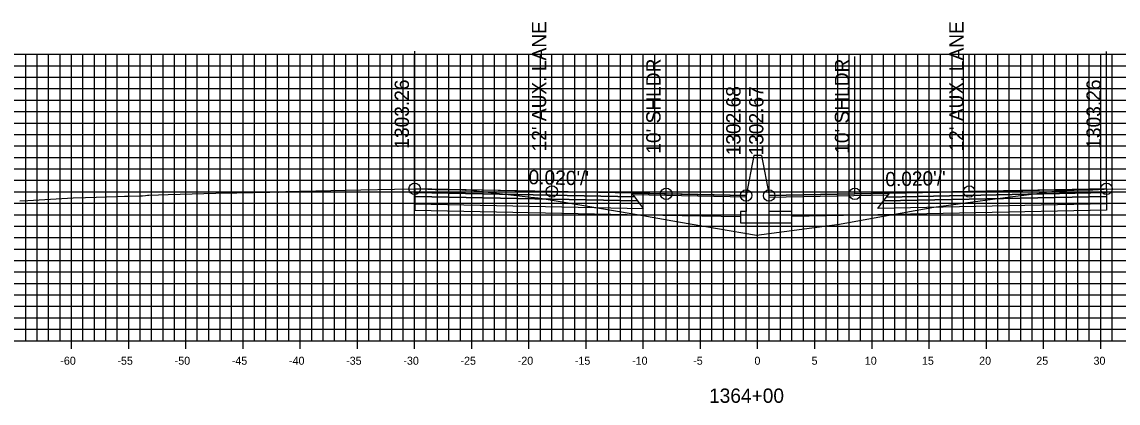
# Model space of a CAD drawing. Extents: x 674939 to 678919, y 750652 to 765176.
# Drawn here: x 678674.2 to 678770, y 754207.1 to 754240.4 of the extents above; entities that cross this region are included whole.
import ezdxf

# ---------------------------------------------------------------- set-up
doc = ezdxf.new("R2010")
doc.units = 0
for name, color, linetype in [('R_Alt Surface', 7, 'Continuous'), ('R_Axis', 7, 'Continuous'), ('R_Axis Annot', 7, 'Continuous'), ('R_Exist Surface', 7, 'Continuous'), ('R_Fin Surface', 7, 'Continuous'), ('R_Grid', 7, 'Continuous'), ('R_No Plot', 7, 'Continuous'), ('R_Proposed Road', 7, 'Continuous'), ('R_Xsect Elev', 7, 'Continuous'), ('R_Xsect Slope', 7, 'Continuous')]:
    doc.layers.add(name, color=color, linetype=linetype)

msp = doc.modelspace()

# ---------------------------------------------------------------- linework, layer by layer
at = {"layer": 'R_Alt Surface'}
for points in [[(678708.541, 754225.481), (678708.541, 754225.151), (678728.041, 754224.761), (678727.791, 754225.096)], [(678769.035, 754225.477), (678769.035, 754225.147), (678749.535, 754224.757), (678749.785, 754225.092)], [(678708.541, 754225.151), (678708.541, 754224.491), (678728.541, 754224.091), (678728.041, 754224.761)], [(678769.035, 754225.147), (678769.035, 754224.487), (678749.035, 754224.087), (678749.535, 754224.757)]]:
    msp.add_lwpolyline(points, close=True, dxfattribs=at)
for points in [[(678708.541, 754224.491), (678708.541, 754223.951), (678728.541, 754223.551), (678737.033, 754223.381)], [(678769.035, 754224.487), (678769.035, 754223.947), (678749.035, 754223.547), (678741.533, 754223.397)]]:
    msp.add_lwpolyline(points, dxfattribs=at)
at = {"layer": 'R_Axis'}
for p, q in [((678678.533, 754211.851), (678678.533, 754213.251)), ((678683.533, 754211.851), (678683.533, 754213.251)), ((678688.533, 754211.851), (678688.533, 754213.251)), ((678693.533, 754211.851), (678693.533, 754213.251)), ((678698.533, 754211.851), (678698.533, 754213.251)), ((678703.533, 754211.851), (678703.533, 754213.251)), ((678708.533, 754211.851), (678708.533, 754213.251)), ((678713.533, 754211.851), (678713.533, 754213.251)), ((678718.533, 754211.851), (678718.533, 754213.251)), ((678723.533, 754211.851), (678723.533, 754213.251)), ((678728.533, 754211.851), (678728.533, 754213.251)), ((678733.533, 754211.851), (678733.533, 754213.251)), ((678738.533, 754211.851), (678738.533, 754213.251)), ((678743.533, 754211.851), (678743.533, 754213.251)), ((678748.533, 754211.851), (678748.533, 754213.251)), ((678753.533, 754211.851), (678753.533, 754213.251)), ((678758.533, 754211.851), (678758.533, 754213.251)), ((678763.533, 754211.851), (678763.533, 754213.251)), ((678768.533, 754211.851), (678768.533, 754213.251)), ((678638.533, 754212.551), (678838.533, 754212.551))]:
    msp.add_line(p, q, dxfattribs=at)
at = {"layer": 'R_Exist Surface'}
msp.add_lwpolyline([(678673.999, 754224.758), (678674.713, 754224.799), (678678.665, 754225.008), (678679.762, 754225.051), (678682.52, 754225.137), (678683.178, 754225.161), (678683.562, 754225.167), (678684.578, 754225.193), (678684.733, 754225.203), (678684.998, 754225.231), (678685.168, 754225.249), (678685.288, 754225.257), (678686.989, 754225.307), (678692.214, 754225.446), (678692.982, 754225.461), (678695.885, 754225.521), (678696.434, 754225.534), (678696.579, 754225.513), (678696.633, 754225.508), (678697.069, 754225.559), (678697.288, 754225.577), (678703.822, 754225.711), (678706.783, 754225.776), (678708.456, 754225.812), (678708.541, 754225.811), (678708.61, 754225.812), (678708.744, 754225.809), (678709.018, 754225.797), (678710.324, 754225.755), (678710.599, 754225.757), (678710.763, 754225.747), (678712.65, 754225.708), (678712.979, 754225.698), (678713.034, 754225.693), (678713.163, 754225.731), (678713.208, 754225.732), (678718.707, 754225.088), (678719.337, 754225.022), (678721.098, 754224.728), (678727.997, 754223.552), (678731.621, 754222.937), (678738.446, 754221.755), (678743.262, 754222.411), (678745.702, 754222.716), (678748.719, 754223.267), (678753.939, 754224.213), (678757.983, 754224.76), (678760.614, 754225.114), (678762.283, 754225.313), (678764.89, 754225.656), (678764.959, 754225.64), (678766.212, 754225.692), (678766.943, 754225.715), (678767.831, 754225.733), (678768.343, 754225.743), (678768.828, 754225.785), (678769.035, 754225.807), (678769.057, 754225.809), (678769.07, 754225.81), (678771.354, 754225.772)], dxfattribs=at)
at = {"layer": 'R_Fin Surface'}
for points in [[(678737.533, 754225.231), (678730.541, 754225.371), (678720.541, 754225.571), (678708.541, 754225.811)], [(678769.035, 754225.807), (678757.035, 754225.567), (678747.035, 754225.367), (678739.533, 754225.217)]]:
    msp.add_lwpolyline(points, dxfattribs=at)
for points in [[(678708.541, 754225.811), (678708.541, 754225.481), (678727.791, 754225.096), (678727.541, 754225.431)], [(678727.541, 754225.431), (678737.533, 754225.231), (678737.537, 754225.073), (678727.661, 754225.271)], [(678749.916, 754225.267), (678739.533, 754225.059), (678739.533, 754225.217), (678750.035, 754225.427)], [(678769.035, 754225.807), (678769.035, 754225.477), (678749.785, 754225.092), (678750.035, 754225.427)]]:
    msp.add_lwpolyline(points, close=True, dxfattribs=at)
at = {"layer": 'R_Grid'}
for p, q in [((678638.533, 754237.551), (678838.533, 754237.551)), ((678674.533, 754212.551), (678674.533, 754237.551)), ((678675.533, 754212.551), (678675.533, 754237.551)), ((678676.533, 754212.551), (678676.533, 754237.551)), ((678677.533, 754212.551), (678677.533, 754237.551)), ((678678.533, 754212.551), (678678.533, 754237.551)), ((678679.533, 754212.551), (678679.533, 754237.551)), ((678680.533, 754212.551), (678680.533, 754237.551)), ((678681.533, 754212.551), (678681.533, 754237.551)), ((678682.533, 754212.551), (678682.533, 754237.551)), ((678683.533, 754212.551), (678683.533, 754237.551)), ((678684.533, 754212.551), (678684.533, 754237.551)), ((678685.533, 754212.551), (678685.533, 754237.551)), ((678686.533, 754212.551), (678686.533, 754237.551)), ((678687.533, 754212.551), (678687.533, 754237.551)), ((678688.533, 754212.551), (678688.533, 754237.551)), ((678689.533, 754212.551), (678689.533, 754237.551)), ((678690.533, 754212.551), (678690.533, 754237.551)), ((678691.533, 754212.551), (678691.533, 754237.551)), ((678692.533, 754212.551), (678692.533, 754237.551)), ((678693.533, 754212.551), (678693.533, 754237.551)), ((678694.533, 754212.551), (678694.533, 754237.551)), ((678695.533, 754212.551), (678695.533, 754237.551)), ((678696.533, 754212.551), (678696.533, 754237.551)), ((678697.533, 754212.551), (678697.533, 754237.551)), ((678698.533, 754212.551), (678698.533, 754237.551)), ((678699.533, 754212.551), (678699.533, 754237.551)), ((678700.533, 754212.551), (678700.533, 754237.551)), ((678701.533, 754212.551), (678701.533, 754237.551)), ((678702.533, 754212.551), (678702.533, 754237.551)), ((678703.533, 754212.551), (678703.533, 754237.551)), ((678704.533, 754212.551), (678704.533, 754237.551)), ((678705.533, 754212.551), (678705.533, 754237.551)), ((678706.533, 754212.551), (678706.533, 754237.551)), ((678707.533, 754212.551), (678707.533, 754237.551)), ((678708.533, 754212.551), (678708.533, 754237.551)), ((678709.533, 754212.551), (678709.533, 754237.551)), ((678710.533, 754212.551), (678710.533, 754237.551)), ((678711.533, 754212.551), (678711.533, 754237.551)), ((678712.533, 754212.551), (678712.533, 754237.551)), ((678713.533, 754212.551), (678713.533, 754237.551)), ((678714.533, 754212.551), (678714.533, 754237.551)), ((678715.533, 754212.551), (678715.533, 754237.551)), ((678716.533, 754212.551), (678716.533, 754237.551)), ((678717.533, 754212.551), (678717.533, 754237.551)), ((678718.533, 754212.551), (678718.533, 754237.551)), ((678719.533, 754212.551), (678719.533, 754237.551)), ((678720.533, 754212.551), (678720.533, 754237.551)), ((678721.533, 754212.551), (678721.533, 754237.551)), ((678722.533, 754212.551), (678722.533, 754237.551)), ((678723.533, 754212.551), (678723.533, 754237.551)), ((678724.533, 754212.551), (678724.533, 754237.551)), ((678725.533, 754212.551), (678725.533, 754237.551)), ((678726.533, 754212.551), (678726.533, 754237.551)), ((678727.533, 754212.551), (678727.533, 754237.551)), ((678728.533, 754212.551), (678728.533, 754237.551)), ((678729.533, 754212.551), (678729.533, 754237.551)), ((678730.533, 754212.551), (678730.533, 754237.551)), ((678731.533, 754212.551), (678731.533, 754237.551)), ((678732.533, 754212.551), (678732.533, 754237.551)), ((678733.533, 754212.551), (678733.533, 754237.551)), ((678734.533, 754212.551), (678734.533, 754237.551)), ((678735.533, 754212.551), (678735.533, 754237.551)), ((678736.533, 754212.551), (678736.533, 754237.551)), ((678737.533, 754212.551), (678737.533, 754237.551)), ((678738.533, 754212.551), (678738.533, 754237.551)), ((678739.533, 754212.551), (678739.533, 754237.551)), ((678740.533, 754212.551), (678740.533, 754237.551)), ((678741.533, 754212.551), (678741.533, 754237.551)), ((678742.533, 754212.551), (678742.533, 754237.551)), ((678743.533, 754212.551), (678743.533, 754237.551)), ((678744.533, 754212.551), (678744.533, 754237.551)), ((678745.533, 754212.551), (678745.533, 754237.551)), ((678746.533, 754212.551), (678746.533, 754237.551)), ((678747.533, 754212.551), (678747.533, 754237.551)), ((678748.533, 754212.551), (678748.533, 754237.551)), ((678749.533, 754212.551), (678749.533, 754237.551)), ((678750.533, 754212.551), (678750.533, 754237.551)), ((678751.533, 754212.551), (678751.533, 754237.551)), ((678752.533, 754212.551), (678752.533, 754237.551)), ((678753.533, 754212.551), (678753.533, 754237.551)), ((678754.533, 754212.551), (678754.533, 754237.551)), ((678755.533, 754212.551), (678755.533, 754237.551)), ((678756.533, 754212.551), (678756.533, 754237.551)), ((678757.533, 754212.551), (678757.533, 754237.551)), ((678758.533, 754212.551), (678758.533, 754237.551)), ((678759.533, 754212.551), (678759.533, 754237.551)), ((678760.533, 754212.551), (678760.533, 754237.551)), ((678761.533, 754212.551), (678761.533, 754237.551)), ((678762.533, 754212.551), (678762.533, 754237.551)), ((678763.533, 754212.551), (678763.533, 754237.551)), ((678764.533, 754212.551), (678764.533, 754237.551)), ((678765.533, 754212.551), (678765.533, 754237.551)), ((678766.533, 754212.551), (678766.533, 754237.551)), ((678767.533, 754212.551), (678767.533, 754237.551)), ((678768.533, 754212.551), (678768.533, 754237.551)), ((678769.533, 754212.551), (678769.533, 754237.551)), ((678638.533, 754236.551), (678838.533, 754236.551)), ((678638.533, 754235.551), (678838.533, 754235.551)), ((678638.533, 754234.551), (678838.533, 754234.551)), ((678638.533, 754233.551), (678838.533, 754233.551)), ((678638.533, 754232.551), (678838.533, 754232.551)), ((678638.533, 754231.551), (678838.533, 754231.551)), ((678638.533, 754230.551), (678838.533, 754230.551)), ((678638.533, 754229.551), (678838.533, 754229.551)), ((678638.533, 754228.551), (678838.533, 754228.551)), ((678638.533, 754227.551), (678838.533, 754227.551)), ((678638.533, 754226.551), (678838.533, 754226.551)), ((678638.533, 754225.551), (678838.533, 754225.551)), ((678638.533, 754224.551), (678838.533, 754224.551)), ((678638.533, 754223.551), (678838.533, 754223.551)), ((678638.533, 754222.551), (678838.533, 754222.551)), ((678638.533, 754221.551), (678838.533, 754221.551)), ((678638.533, 754220.551), (678838.533, 754220.551)), ((678638.533, 754219.551), (678838.533, 754219.551)), ((678638.533, 754218.551), (678838.533, 754218.551)), ((678638.533, 754217.551), (678838.533, 754217.551)), ((678638.533, 754216.551), (678838.533, 754216.551)), ((678638.533, 754215.551), (678838.533, 754215.551)), ((678638.533, 754214.551), (678838.533, 754214.551)), ((678638.533, 754213.551), (678838.533, 754213.551)), ((678638.533, 754212.551), (678838.533, 754212.551))]:
    msp.add_line(p, q, dxfattribs=at)
at = {"layer": 'R_No Plot'}
for centre in [(678708.541, 754225.811), (678769.035, 754225.807), (678720.541, 754225.571), (678730.541, 754225.371), (678737.533, 754225.231), (678739.533, 754225.217), (678747.035, 754225.367), (678757.035, 754225.567)]:
    msp.add_circle(centre, 0.5, dxfattribs=at)
at = {"layer": 'R_Proposed Road'}
for points in [[(678738.203, 754228.731), (678737.533, 754225.231)], [(678738.863, 754228.717), (678738.863, 754228.731), (678738.203, 754228.731), (678738.203, 754228.731)], [(678738.863, 754228.717), (678739.533, 754225.217)], [(678737.533, 754225.231), (678737.533, 754223.842), (678737.033, 754223.842), (678737.033, 754222.842), (678741.533, 754222.842), (678741.533, 754223.842), (678739.533, 754223.842), (678739.533, 754225.217)]]:
    msp.add_lwpolyline(points, dxfattribs=at)
at = {"layer": 'R_Xsect Elev'}
for p, q in [((678708.541, 754225.811), (678708.541, 754237.811)), ((678769.035, 754225.807), (678769.035, 754237.807)), ((678720.541, 754225.571), (678720.541, 754237.571)), ((678730.541, 754225.371), (678730.541, 754237.371)), ((678737.533, 754225.231), (678737.533, 754237.231)), ((678739.533, 754225.217), (678739.533, 754237.217)), ((678747.035, 754225.367), (678747.035, 754237.367)), ((678757.035, 754225.567), (678757.035, 754237.567))]:
    msp.add_line(p, q, dxfattribs=at)

# ---------------------------------------------------------------- texts
at = {"layer": 'R_Axis Annot'}
for s, height, p in [('-60', 0.7, (678677.552, 754210.451)), ('-55', 0.7, (678682.546, 754210.451)), ('-50', 0.7, (678687.552, 754210.451)), ('-45', 0.7, (678692.546, 754210.451)), ('-40', 0.7, (678697.552, 754210.451)), ('-35', 0.7, (678702.546, 754210.451)), ('-30', 0.7, (678707.552, 754210.451)), ('-25', 0.7, (678712.546, 754210.451)), ('-20', 0.7, (678717.552, 754210.451)), ('-15', 0.7, (678722.546, 754210.451)), ('-10', 0.7, (678727.552, 754210.451)), ('-5', 0.7, (678732.896, 754210.451)), ('0', 0.7, (678738.252, 754210.451)), ('5', 0.7, (678743.246, 754210.451)), ('10', 0.7, (678747.902, 754210.451)), ('15', 0.7, (678752.896, 754210.451)), ('20', 0.7, (678757.902, 754210.451)), ('25', 0.7, (678762.896, 754210.451)), ('30', 0.7, (678767.902, 754210.451)), ('1364+00', 1.25, (678734.282, 754207.126))]:
    msp.add_text(s, height=height, dxfattribs=at).set_placement(p)
at = {"layer": 'R_Xsect Elev'}
for s, p in [("12' AUX. LANE", (678720.041, 754229.071)), ("12' AUX. LANE", (678756.535, 754229.067)), ("10' SHLDR", (678730.041, 754228.871)), ("10' SHLDR", (678746.535, 754228.867)), ('1303.26', (678708.041, 754229.311)), ('1303.26', (678768.535, 754229.307)), ('1302.68', (678737.033, 754228.731)), ('1302.67', (678739.033, 754228.717))]:
    msp.add_text(s, height=1.25, rotation=90, dxfattribs=at).set_placement(p)
at = {"layer": 'R_Xsect Slope'}
for rotation, p in [(358.85424, (678718.487, 754226.212)), (1.14576, (678749.71, 754226.02))]:
    msp.add_text("0.020'/'", height=1.25, rotation=rotation, dxfattribs=at).set_placement(p)

doc.saveas('drawing.dxf')
